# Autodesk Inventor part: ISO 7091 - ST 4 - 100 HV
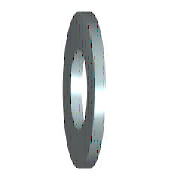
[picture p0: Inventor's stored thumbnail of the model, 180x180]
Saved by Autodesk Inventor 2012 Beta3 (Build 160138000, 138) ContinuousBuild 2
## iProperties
IsCustomPart: 0
Created: 2010-02
Part Number: ISO 7091 - ST 4 - 100 HV
Material: Steel
Description: Plain washers - Normal series - Product grade C
Document SubType Name: Modeling
Standard: ISO 7091
Designer: Thom Tremblay
Standard Revision: Second edition 2000-06-01
Standards Organization: ISO
Language: en-US
Size Designation: ST 4 - 100 HV
Categories: <MemberInstance><Categories><Category DisplayName="Fasteners" InternalName="e4da775c-781d-43d5-af7c-5136215cf5a6" Mnemonic="FSTN"><Category DisplayName="Washers
Density: 7.85 g/cm^3
Author: Thom Tremblay
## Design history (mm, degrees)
body "Solid1"
sketch "Sketch"
  geometry: C1 r 5 at (0, 0); C2 r 2.25 at (0, 0); 1 further point
  constraints: 2 centre point, 2 coincident
  dimensions: "d0" = 4.5 diameter of C2 (= SD1); "d1" = 10 diameter of C1 (= SD2)
extrude "Body" new body sketch "Sketch" distance "d2" = 1 (= SD); taper "d3" = 0 deg
workaxis "Work Axis1"
workplane "Work Plane1"
other parameters: "SD1" = 4.5 [user parameter; used in 1 equation term], "SD2" = 10 [user parameter; used in 1 equation term], "SD" = 1 [user parameter; used in 1 equation term], "d4" = 0, "d5" = 0, "d6" = 0, "d7" = 0, "NND" = 4 [user parameter]
